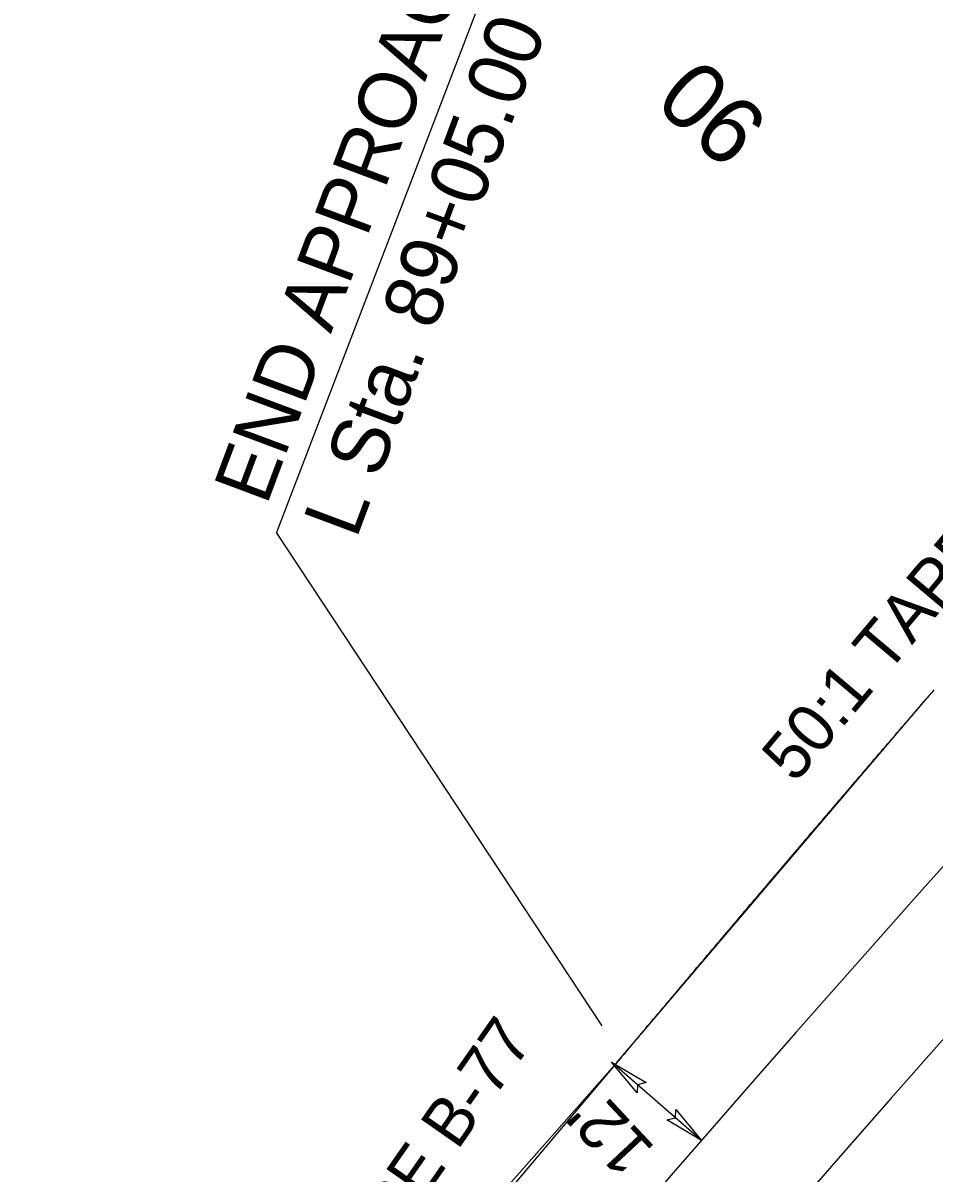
# Model space of a CAD drawing. Extents: x 2389694 to 2405615, y 546931 to 573532.
# Drawn here: x 2395977.9 to 2396073.1, y 557817.6 to 557937.6 of the extents above; entities that cross this region are included whole.
import ezdxf

# ---------------------------------------------------------------- set-up
doc = ezdxf.new("R2010")
doc.units = 0
for name, color, linetype in [('Old_Level_11', 7, 'Continuous'), ('Prop Dimension', 7, 'Continuous'), ('Prop Dimension Text', 7, 'Continuous'), ('Prop EOT', 7, 'Continuous'), ('Prop Guardrail', 7, 'Continuous'), ('Prop Horizontal Alignment', 7, 'Continuous'), ('Prop Horizontal Alignment Curve and Spiral Data', 7, 'Continuous'), ('Prop Lane Lines', 7, 'Continuous')]:
    doc.layers.add(name, color=color, linetype=linetype)

# ---------------------------------------------------------------- blocks, each defined once
blk = doc.blocks.new('TERM')
at = {"layer": 'Old_Level_11'}
blk.add_lwpolyline([(-0.01375, 0.00225), (0, 0), (-0.01375, -0.0025), (-0.012, 0)], close=True, dxfattribs=at)

msp = doc.modelspace()

# ---------------------------------------------------------------- linework, layer by layer
at = {"layer": 'Prop Dimension'}
for p, q in [((2396041.71, 557981.73), (2396004.42, 557884.45)), ((2396038.46, 557832.96), (2396004.42, 557884.45)), ((2396048.82, 557820.98), (2396039.44, 557829.17))]:
    msp.add_line(p, q, dxfattribs=at)
at = {"layer": 'Prop EOT'}
for p, q in [((2396040.03, 557829.17), (2396072.21, 557866.97)), ((2396027.35, 557814.84), (2396040.03, 557829.17))]:
    msp.add_line(p, q, dxfattribs=at)
for radius, end in [(3559, 163.17888), (3523, 169.40696), (3453, 155.44499), (3429, 155.44499)]:
    msp.add_arc((2398729.82, 555480.32), radius, 136.54853, end, dxfattribs=at)
at = {"layer": 'Prop Guardrail'}
msp.add_line((2396040.03, 557829.17), (2396023.3, 557809.4), dxfattribs=at)
msp.add_spline([(2396073.11, 557868.02), (2396072.66, 557867.5), (2396072.21, 557866.97), (2396071.76, 557866.45), (2396071.31, 557865.93), (2396070.86, 557865.41), (2396070.41, 557864.89), (2396069.96, 557864.36), (2396069.51, 557863.84), (2396069.06, 557863.32), (2396068.61, 557862.79), (2396068.16, 557862.27), (2396067.71, 557861.75), (2396067.26, 557861.23), (2396066.81, 557860.7), (2396066.36, 557860.18), (2396065.91, 557859.66), (2396065.46, 557859.13), (2396065.01, 557858.61), (2396064.57, 557858.09), (2396064.12, 557857.56), (2396063.67, 557857.04), (2396063.22, 557856.52), (2396062.77, 557855.99), (2396062.32, 557855.47), (2396061.87, 557854.94), (2396061.43, 557854.42), (2396060.98, 557853.9), (2396060.53, 557853.37), (2396060.08, 557852.85), (2396059.63, 557852.32), (2396059.19, 557851.8), (2396058.74, 557851.27), (2396058.29, 557850.75), (2396057.84, 557850.22), (2396057.4, 557849.7), (2396056.95, 557849.17), (2396056.5, 557848.65), (2396056.05, 557848.12), (2396055.61, 557847.6), (2396055.16, 557847.07), (2396054.71, 557846.55), (2396054.27, 557846.02), (2396053.82, 557845.5), (2396053.37, 557844.97), (2396052.93, 557844.45), (2396052.48, 557843.92), (2396052.04, 557843.39), (2396051.59, 557842.87), (2396051.14, 557842.34), (2396050.7, 557841.82), (2396050.25, 557841.29), (2396049.81, 557840.76), (2396049.36, 557840.24), (2396048.92, 557839.71), (2396048.47, 557839.18), (2396048.02, 557838.66), (2396047.58, 557838.13), (2396047.13, 557837.6), (2396046.69, 557837.08), (2396046.25, 557836.55), (2396045.8, 557836.02), (2396045.36, 557835.5), (2396044.91, 557834.97), (2396044.47, 557834.44), (2396044.02, 557833.92), (2396043.58, 557833.39), (2396043.13, 557832.86), (2396042.69, 557832.33), (2396042.25, 557831.8), (2396041.8, 557831.28), (2396041.36, 557830.75), (2396040.92, 557830.22), (2396040.03, 557829.17)], degree=3, dxfattribs=at)
at = {"layer": 'Prop Horizontal Alignment'}
msp.add_arc((2398729.82, 555480.32), 3500, 136.54853, 177.15578, dxfattribs=at)
at = {"layer": 'Prop Lane Lines'}
for radius, end in [(3547, 169.40696), (3535, 169.40696), (3441, 155.44499)]:
    msp.add_arc((2398729.82, 555480.32), radius, 136.54853, end, dxfattribs=at)

# ---------------------------------------------------------------- block references
at = {"layer": 'Prop Dimension', "xscale": 300.00000000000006, "yscale": 300.00000000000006}
for p, rotation in [((2396039.44, 557829.17), 138.87725307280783), ((2396048.82, 557820.98), -41.122746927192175)]:
    msp.add_blockref('TERM', p, dxfattribs=dict(at, rotation=rotation))

# ---------------------------------------------------------------- texts
at = {"layer": 'Prop Dimension Text'}
for s, height, rotation, p in [('END APPROACH SLAB', 6, 69.5025, (2396003.39, 557887.17)), ('L Sta. 89+05.00', 6, 69.5025, (2396012.76, 557883.67)), ('50:1 TAPER', 5, 49.891, (2396058.59, 557858.16)), ('TYPE B-77', 5, 55.0725, (2396012.26, 557804.02)), ("12'", 5, 133.1053, (2396044.11, 557820.15))]:
    msp.add_text(s, height=height, rotation=rotation, dxfattribs=at).set_placement(p)
at = {"layer": 'Prop Horizontal Alignment Curve and Spiral Data'}
msp.add_text('90', height=7, rotation=137.6229, dxfattribs=at).set_placement((2396056.15, 557927.31))

doc.saveas('drawing.dxf')
